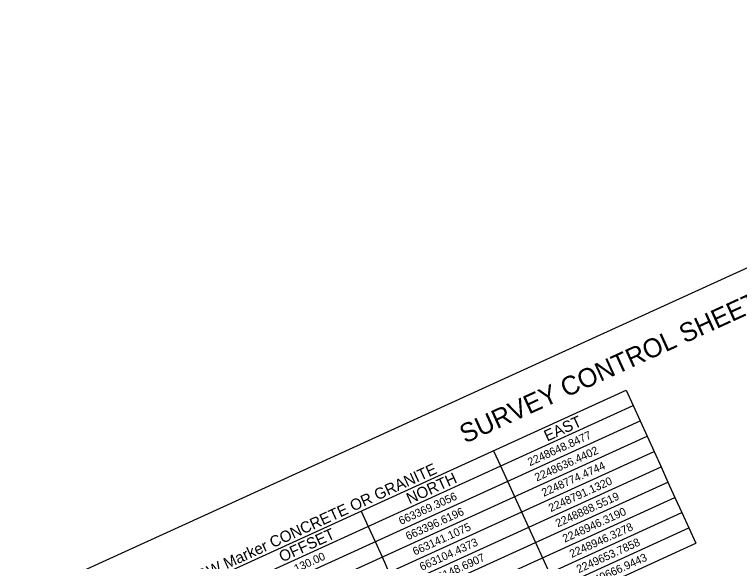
# Model space of a CAD drawing. Extents: x 2253388 to 2258607, y 664121 to 668933.
# Drawn here: x 2253510 to 2255684, y 667208 to 668849 of the extents above; entities that cross this region are included whole.
import ezdxf

# ---------------------------------------------------------------- set-up
doc = ezdxf.new("R2010")
doc.units = 0
for name, color, linetype in [('CTL Sheet Border CELL', 7, 'Continuous'), ('CTL Sheet Notes CELL', 7, 'Continuous'), ('CTL Sheet Table Cell', 7, 'Continuous'), ('CTL Sheet Text', 7, 'Continuous')]:
    doc.layers.add(name, color=color, linetype=linetype)

msp = doc.modelspace()

# ---------------------------------------------------------------- linework, layer by layer
at = {"layer": 'CTL Sheet Border CELL'}
msp.add_lwpolyline([(2257373.5, 668848.7), (2253509.6, 667086.2), (2254743.3, 664381.5), (2258607.2, 666143.9)], close=True, dxfattribs=at)
at = {"layer": 'CTL Sheet Table Cell'}
for p, q in [((2253631.7, 666941.5), (2255343.9, 667721.8)), ((2255343.9, 667721.8), (2255364.8, 667675.9)), ((2253652.6, 666895.7), (2255364.8, 667675.9)), ((2255364.8, 667675.9), (2255385.7, 667630)), ((2253673.5, 666849.8), (2255385.7, 667630)), ((2255385.7, 667630), (2255406.6, 667584.2)), ((2253694.4, 666803.9), (2255406.6, 667584.2)), ((2255406.6, 667584.2), (2255427.5, 667538.3)), ((2253715.3, 666758.1), (2255427.5, 667538.3)), ((2254946.4, 667540.6), (2254967.3, 667494.8)), ((2255427.5, 667538.3), (2255448.4, 667492.4)), ((2254967.3, 667494.8), (2254988.2, 667448.9)), ((2253736.2, 666712.2), (2255448.4, 667492.4)), ((2255448.4, 667492.4), (2255469.3, 667446.6)), ((2253757.1, 666666.4), (2255469.3, 667446.6)), ((2254988.2, 667448.9), (2255009.1, 667403)), ((2255469.3, 667446.6), (2255490.2, 667400.7)), ((2253778, 666620.5), (2255490.2, 667400.7)), ((2255009.1, 667403), (2255030, 667357.2)), ((2255490.2, 667400.7), (2255511.1, 667354.9)), ((2253798.9, 666574.6), (2255511.1, 667354.9)), ((2254549, 667359.5), (2254569.9, 667313.7)), ((2255030, 667357.2), (2255050.9, 667311.3)), ((2255511.1, 667354.9), (2255532, 667309)), ((2253819.8, 666528.8), (2255532, 667309)), ((2254569.9, 667313.7), (2254590.8, 667267.8)), ((2255050.9, 667311.3), (2255071.8, 667265.5)), ((2255532, 667309), (2255552.9, 667263.1)), ((2253840.7, 666482.9), (2255552.9, 667263.1)), ((2254590.8, 667267.8), (2254611.7, 667221.9)), ((2255071.8, 667265.5), (2255092.7, 667219.6)), ((2254611.7, 667221.9), (2254632.6, 667176.1)), ((2255092.7, 667219.6), (2255113.6, 667173.7))]:
    msp.add_line(p, q, dxfattribs=at)

# ---------------------------------------------------------------- texts
at = {"layer": 'CTL Sheet Border CELL'}
msp.add_text('SURVEY CONTROL SHEET I3318BB', height=56.625, rotation=24.5191, dxfattribs=at).set_placement((2254860.8, 667561.4))
at = {"layer": 'CTL Sheet Notes CELL'}
for s, p in [('EAST', (2255107, 667567.6)), ('ROW Marker CONCRETE OR GRANITE', (2254034.4, 667134.3)), ('NORTH', (2254694.3, 667379.6)), ('OFFSET', (2254312.3, 667205.5))]:
    msp.add_text(s, height=33.6, rotation=24.4979, dxfattribs=at).set_placement(p)
at = {"layer": 'CTL Sheet Text'}
for s, p in [('2248648.8477', (2255055.1, 667493.9)), ('2248636.4402', (2255076, 667448)), ('2248774.4744', (2255096.9, 667402.2)), ('2248791.1320', (2255117.8, 667356.3)), ('663369.3056', (2254668.5, 667317.7)), ('2248888.5519', (2255138.7, 667310.4)), ('663396.6196', (2254689.4, 667271.8)), ('2248946.3190', (2255159.6, 667264.6)), ('663141.1075', (2254710.3, 667226)), ('2248946.3278', (2255180.5, 667218.7)), ('663104.4373', (2254731.2, 667180.1)), ('2249653.7858', (2255201.4, 667172.8)), ('-130.00', (2254344.9, 667170.3)), ('663148.6907', (2254752.1, 667134.3)), ('2249666.9443', (2255222.3, 667127))]:
    msp.add_text(s, height=24, rotation=24.4979, dxfattribs=at).set_placement(p)

doc.saveas('drawing.dxf')
